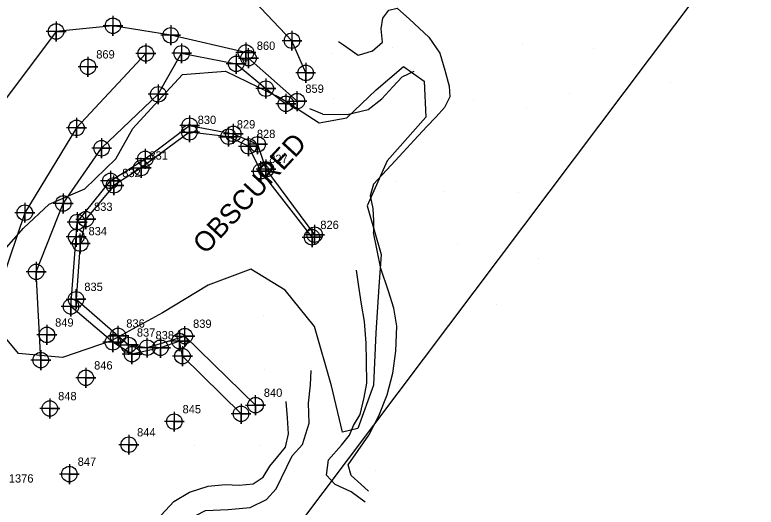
# Model space of a CAD drawing. Extents: x 1497074 to 1501343, y 481943 to 486114.
# Drawn here: x 1498929.9 to 1499153.8, y 484967.5 to 485116.2 of the extents above; entities that cross this region are included whole.
import ezdxf

# ---------------------------------------------------------------- set-up
doc = ezdxf.new("R2010")
doc.units = 0
for name, color, linetype in [('Exist DTM Breakline', 7, 'Continuous'), ('Exist DTM Breakline Cogo Point CELL', 7, 'Continuous'), ('Exist DTM Regular Point CELL', 7, 'Continuous'), ('Exist DTM Regular Point Cogo Number', 7, 'Continuous'), ('Exist Hydro Stream or Body of Water', 7, 'Continuous'), ('Exist Hydro Stream or Body of Water Cogo Number', 7, 'Continuous'), ('Exist Hydro Stream or Body of Water Cogo Point CELL', 7, 'Continuous'), ('PH Exist DTM Boundary', 7, 'Continuous'), ('PH Exist DTM Breakline', 7, 'Continuous'), ('PH Exist DTM Obscure Area', 7, 'Continuous'), ('PH Exist DTM Obscure Area Text', 7, 'Continuous'), ('PH Exist DTM Point', 7, 'Continuous')]:
    doc.layers.add(name, color=color, linetype=linetype)

msp = doc.modelspace()

# ---------------------------------------------------------------- linework, layer by layer
at = {"layer": 'Exist DTM Breakline'}
for points in [[(1499017.74, 485098.64), (1499013.59, 485108.36), (1499002.23, 485120.24), (1498990.16, 485123.16), (1498988.61, 485135.66), (1498984.96, 485153.78)], [(1498999.68, 485104.8), (1498976.97, 485110), (1498959.54, 485112.86), (1498942.37, 485111.16), (1498921.51, 485083.5), (1498907.1, 485054.38), (1498898.24, 485021.36), (1498896.28, 484993.61), (1498898.08, 484985.39)], [(1498969.44, 485104.51), (1498948.52, 485082.03), (1498932.91, 485056.44), (1498921.14, 485021.92), (1498922.42, 484992.91)], [(1498937.73, 485011.92), (1498936.35, 485038.58), (1498944.53, 485059.22), (1498956.11, 485075.89), (1498973.21, 485092.17), (1498980.28, 485104.56), (1498996.74, 485101.37), (1499005.7, 485093.9), (1499011.75, 485089.32)], [(1498979.63, 485017.67), (1498973.87, 485015.66), (1498965.28, 485013.72), (1498959.5, 485017.32), (1498946.85, 485028.12), (1498948.44, 485049.1), (1498948.75, 485053.61), (1498958.76, 485066.03), (1498969.3, 485072.7), (1498982.69, 485082.73), (1498995.88, 485080.22), (1499003.22, 485077.09), (1499005.74, 485069.54), (1499020.42, 485049.78)], [(1498998.21, 484995.71), (1498980.52, 485013.12), (1498979.63, 485017.67)]]:
    msp.add_lwpolyline(points, dxfattribs=at)
at = {"layer": 'Exist DTM Breakline Cogo Point CELL'}
for points in [[(1498959.54, 485115.86), (1498959.54, 485109.86), (1498959.54, 485112.86), (1498962.54, 485112.86), (1498956.54, 485112.86)], [(1498942.37, 485114.16), (1498942.37, 485108.16), (1498942.37, 485111.16), (1498945.37, 485111.16), (1498939.37, 485111.16)], [(1498976.97, 485113), (1498976.97, 485107), (1498976.97, 485110), (1498979.97, 485110), (1498973.97, 485110)], [(1499013.59, 485111.36), (1499013.59, 485105.36), (1499013.59, 485108.36), (1499016.59, 485108.36), (1499010.59, 485108.36)], [(1498969.44, 485107.51), (1498969.44, 485101.51), (1498969.44, 485104.51), (1498972.44, 485104.51), (1498966.44, 485104.51)], [(1498980.28, 485107.56), (1498980.28, 485101.56), (1498980.28, 485104.56), (1498983.28, 485104.56), (1498977.28, 485104.56)], [(1498999.68, 485107.8), (1498999.68, 485101.8), (1498999.68, 485104.8), (1499002.68, 485104.8), (1498996.68, 485104.8)], [(1498996.74, 485104.37), (1498996.74, 485098.37), (1498996.74, 485101.37), (1498999.74, 485101.37), (1498993.74, 485101.37)], [(1499017.74, 485101.64), (1499017.74, 485095.64), (1499017.74, 485098.64), (1499020.74, 485098.64), (1499014.74, 485098.64)], [(1498973.21, 485095.17), (1498973.21, 485089.17), (1498973.21, 485092.17), (1498976.21, 485092.17), (1498970.21, 485092.17)], [(1499005.7, 485096.9), (1499005.7, 485090.9), (1499005.7, 485093.9), (1499008.7, 485093.9), (1499002.7, 485093.9)], [(1499011.75, 485092.32), (1499011.75, 485086.32), (1499011.75, 485089.32), (1499014.75, 485089.32), (1499008.75, 485089.32)], [(1498948.52, 485085.03), (1498948.52, 485079.03), (1498948.52, 485082.03), (1498951.52, 485082.03), (1498945.52, 485082.03)], [(1498982.69, 485085.73), (1498982.69, 485079.73), (1498982.69, 485082.73), (1498985.69, 485082.73), (1498979.69, 485082.73)], [(1498995.88, 485083.22), (1498995.88, 485077.22), (1498995.88, 485080.22), (1498998.88, 485080.22), (1498992.88, 485080.22)], [(1499003.22, 485080.09), (1499003.22, 485074.09), (1499003.22, 485077.09), (1499006.22, 485077.09), (1499000.22, 485077.09)], [(1498956.11, 485078.89), (1498956.11, 485072.89), (1498956.11, 485075.89), (1498959.11, 485075.89), (1498953.11, 485075.89)], [(1498969.3, 485075.7), (1498969.3, 485069.7), (1498969.3, 485072.7), (1498972.3, 485072.7), (1498966.3, 485072.7)], [(1499005.74, 485072.54), (1499005.74, 485066.54), (1499005.74, 485069.54), (1499008.74, 485069.54), (1499002.74, 485069.54)], [(1498958.76, 485069.03), (1498958.76, 485063.03), (1498958.76, 485066.03), (1498961.76, 485066.03), (1498955.76, 485066.03)], [(1498944.53, 485062.22), (1498944.53, 485056.22), (1498944.53, 485059.22), (1498947.53, 485059.22), (1498941.53, 485059.22)], [(1498932.91, 485059.44), (1498932.91, 485053.44), (1498932.91, 485056.44), (1498935.91, 485056.44), (1498929.91, 485056.44)], [(1498948.75, 485056.61), (1498948.75, 485050.61), (1498948.75, 485053.61), (1498951.75, 485053.61), (1498945.75, 485053.61)], [(1499020.42, 485052.78), (1499020.42, 485046.78), (1499020.42, 485049.78), (1499023.42, 485049.78), (1499017.42, 485049.78)], [(1498948.44, 485052.1), (1498948.44, 485046.1), (1498948.44, 485049.1), (1498951.44, 485049.1), (1498945.44, 485049.1)], [(1498936.35, 485041.58), (1498936.35, 485035.58), (1498936.35, 485038.58), (1498939.35, 485038.58), (1498933.35, 485038.58)], [(1498946.85, 485031.12), (1498946.85, 485025.12), (1498946.85, 485028.12), (1498949.85, 485028.12), (1498943.85, 485028.12)], [(1498959.5, 485020.32), (1498959.5, 485014.32), (1498959.5, 485017.32), (1498962.5, 485017.32), (1498956.5, 485017.32)], [(1498979.63, 485020.67), (1498979.63, 485014.67), (1498979.63, 485017.67), (1498982.63, 485017.67), (1498976.63, 485017.67)], [(1498965.28, 485016.72), (1498965.28, 485010.72), (1498965.28, 485013.72), (1498968.28, 485013.72), (1498962.28, 485013.72)], [(1498973.87, 485018.66), (1498973.87, 485012.66), (1498973.87, 485015.66), (1498976.87, 485015.66), (1498970.87, 485015.66)], [(1498937.73, 485014.92), (1498937.73, 485008.92), (1498937.73, 485011.92), (1498940.73, 485011.92), (1498934.73, 485011.92)], [(1498980.52, 485016.12), (1498980.52, 485010.12), (1498980.52, 485013.12), (1498983.52, 485013.12), (1498977.52, 485013.12)], [(1498998.21, 484998.71), (1498998.21, 484992.71), (1498998.21, 484995.71), (1499001.21, 484995.71), (1498995.21, 484995.71)]]:
    msp.add_lwpolyline(points, dxfattribs=at)
for centre in [(1498959.54, 485112.86), (1498942.37, 485111.16), (1498976.97, 485110), (1499013.59, 485108.36), (1498969.44, 485104.51), (1498980.28, 485104.56), (1498999.68, 485104.8), (1498996.74, 485101.37), (1499017.74, 485098.64), (1499005.7, 485093.9), (1498973.21, 485092.17), (1499011.75, 485089.32), (1498948.52, 485082.03), (1498982.69, 485082.73), (1498995.88, 485080.22), (1499003.22, 485077.09), (1498956.11, 485075.89), (1498969.3, 485072.7), (1499005.74, 485069.54), (1498958.76, 485066.03), (1498944.53, 485059.22), (1498932.91, 485056.44), (1498948.75, 485053.61), (1498948.44, 485049.1), (1499020.42, 485049.78), (1498936.35, 485038.58), (1498946.85, 485028.12), (1498959.5, 485017.32), (1498979.63, 485017.67), (1498973.87, 485015.66), (1498965.28, 485013.72), (1498980.52, 485013.12), (1498937.73, 485011.92), (1498998.21, 484995.71)]:
    msp.add_circle(centre, 2.34, dxfattribs=at)
at = {"layer": 'Exist DTM Regular Point CELL'}
for points in [[(1498951.99, 485103.49), (1498951.99, 485097.49), (1498951.99, 485100.49), (1498954.99, 485100.49), (1498948.99, 485100.49)], [(1498939.58, 485022.54), (1498939.58, 485016.54), (1498939.58, 485019.54), (1498942.58, 485019.54), (1498936.58, 485019.54)], [(1498951.35, 485009.59), (1498951.35, 485003.59), (1498951.35, 485006.59), (1498954.35, 485006.59), (1498948.35, 485006.59)], [(1498940.48, 485000.32), (1498940.48, 484994.32), (1498940.48, 484997.32), (1498943.48, 484997.32), (1498937.48, 484997.32)], [(1498978.05, 484996.36), (1498978.05, 484990.36), (1498978.05, 484993.36), (1498981.05, 484993.36), (1498975.05, 484993.36)], [(1498964.32, 484989.39), (1498964.32, 484983.39), (1498964.32, 484986.39), (1498967.32, 484986.39), (1498961.32, 484986.39)], [(1498946.38, 484980.51), (1498946.38, 484974.51), (1498946.38, 484977.51), (1498949.38, 484977.51), (1498943.38, 484977.51)]]:
    msp.add_lwpolyline(points, dxfattribs=at)
for centre in [(1498951.99, 485100.49), (1498939.58, 485019.54), (1498951.35, 485006.59), (1498940.48, 484997.32), (1498978.05, 484993.36), (1498964.32, 484986.39), (1498946.38, 484977.51)]:
    msp.add_circle(centre, 2.34, dxfattribs=at)
at = {"layer": 'Exist Hydro Stream or Body of Water'}
msp.add_line((1499015.12, 485090.12), (1499000.46, 485103.1), dxfattribs=at)
msp.add_lwpolyline([(1499019.65, 485049.02), (1499004.22, 485068.96), (1499000.49, 485076.47), (1498994.43, 485079.37), (1498982.62, 485080.71), (1498968.05, 485069.95), (1498959.84, 485064.68), (1498951.33, 485054.48), (1498949.66, 485047.11), (1498948.39, 485030.3), (1498961.06, 485019.25), (1498964.25, 485016.51), (1498969.89, 485015.7), (1498981.23, 485019.17), (1499002.59, 484998.34)], dxfattribs=at)
at = {"layer": 'Exist Hydro Stream or Body of Water Cogo Point CELL'}
for points in [[(1498997.46, 485103.1), (1499003.46, 485103.1), (1499000.46, 485103.1), (1499000.46, 485100.1), (1499000.46, 485106.1)], [(1499012.12, 485090.12), (1499018.12, 485090.12), (1499015.12, 485090.12), (1499015.12, 485087.12), (1499015.12, 485093.12)], [(1498979.62, 485080.71), (1498985.62, 485080.71), (1498982.62, 485080.71), (1498982.62, 485077.71), (1498982.62, 485083.71)], [(1498991.43, 485079.37), (1498997.43, 485079.37), (1498994.43, 485079.37), (1498994.43, 485076.37), (1498994.43, 485082.37)], [(1498997.49, 485076.47), (1499003.49, 485076.47), (1499000.49, 485076.47), (1499000.49, 485073.47), (1499000.49, 485079.47)], [(1498965.05, 485069.95), (1498971.05, 485069.95), (1498968.05, 485069.95), (1498968.05, 485066.95), (1498968.05, 485072.95)], [(1499001.22, 485068.96), (1499007.22, 485068.96), (1499004.22, 485068.96), (1499004.22, 485065.96), (1499004.22, 485071.96)], [(1498956.84, 485064.68), (1498962.84, 485064.68), (1498959.84, 485064.68), (1498959.84, 485061.68), (1498959.84, 485067.68)], [(1498948.33, 485054.48), (1498954.33, 485054.48), (1498951.33, 485054.48), (1498951.33, 485051.48), (1498951.33, 485057.48)], [(1499016.65, 485049.02), (1499022.65, 485049.02), (1499019.65, 485049.02), (1499019.65, 485046.02), (1499019.65, 485052.02)], [(1498946.66, 485047.11), (1498952.66, 485047.11), (1498949.66, 485047.11), (1498949.66, 485044.11), (1498949.66, 485050.11)], [(1498945.39, 485030.3), (1498951.39, 485030.3), (1498948.39, 485030.3), (1498948.39, 485027.3), (1498948.39, 485033.3)], [(1498958.06, 485019.25), (1498964.06, 485019.25), (1498961.06, 485019.25), (1498961.06, 485016.25), (1498961.06, 485022.25)], [(1498978.23, 485019.17), (1498984.23, 485019.17), (1498981.23, 485019.17), (1498981.23, 485016.17), (1498981.23, 485022.17)], [(1498961.25, 485016.51), (1498967.25, 485016.51), (1498964.25, 485016.51), (1498964.25, 485013.51), (1498964.25, 485019.51)], [(1498966.89, 485015.7), (1498972.89, 485015.7), (1498969.89, 485015.7), (1498969.89, 485012.7), (1498969.89, 485018.7)], [(1498999.59, 484998.34), (1499005.59, 484998.34), (1499002.59, 484998.34), (1499002.59, 484995.34), (1499002.59, 485001.34)]]:
    msp.add_lwpolyline(points, dxfattribs=at)
for centre in [(1499000.46, 485103.1), (1499015.12, 485090.12), (1498982.62, 485080.71), (1498994.43, 485079.37), (1499000.49, 485076.47), (1498968.05, 485069.95), (1499004.22, 485068.96), (1498959.84, 485064.68), (1498951.33, 485054.48), (1499019.65, 485049.02), (1498949.66, 485047.11), (1498948.39, 485030.3), (1498961.06, 485019.25), (1498981.23, 485019.17), (1498964.25, 485016.51), (1498969.89, 485015.7), (1499002.59, 484998.34)]:
    msp.add_circle(centre, 2.34, dxfattribs=at)
at = {"layer": 'PH Exist DTM Boundary'}
msp.add_lwpolyline([(1498924.23, 484841.06), (1498545.19, 485168.9), (1498846.5, 485569.16), (1499227.59, 485244.03)], close=True, dxfattribs=at)
at = {"layer": 'PH Exist DTM Breakline'}
for points in [[(1499037.83, 485105.16), (1499040.94, 485107.91), (1499040.55, 485111.94), (1499041, 485115.16), (1499042.88, 485117.61), (1499045.35, 485118.18), (1499049.03, 485114.84), (1499054.89, 485109.41), (1499058.26, 485104.57), (1499059.74, 485099.51), (1499061.08, 485094.59), (1499061.3, 485091.46), (1499059.68, 485088.23), (1499057.08, 485085.42), (1499054.3, 485082.41), (1499050.52, 485078.33), (1499047.14, 485074.67), (1499043.55, 485070.79), (1499040.79, 485067.83), (1499038.24, 485065.07), (1499037.17, 485061.55), (1499037.99, 485057.71), (1499038.23, 485054.01), (1499038.16, 485050.44)], [(1499037.83, 485105.16), (1499033.53, 485103.91), (1499029.17, 485106.99), (1499027.68, 485108.04)], [(1499022.93, 485086.21), (1499030.28, 485086.1), (1499036.57, 485087.63), (1499040.68, 485090.76), (1499044.05, 485094.4), (1499046.86, 485097.41), (1499050.49, 485099.15)], [(1499022.93, 485086.21), (1499018.99, 485087.82)], [(1499036.7, 484972.33), (1499034.41, 484974.44), (1499031.49, 484977.14), (1499030.58, 484980.35), (1499033.56, 484984.66), (1499036.79, 484989.29), (1499039.83, 484995.06), (1499042.36, 485001.42), (1499044.03, 485008), (1499044.97, 485014.64), (1499045.25, 485022.13), (1499044.32, 485027.62), (1499042.74, 485032.78), (1499040.37, 485039.56), (1499038.16, 485050.44)], [(1499035.67, 484969.09), (1499031.49, 484972.13), (1499026.68, 484974.39), (1499023.97, 484977.18), (1499024.59, 484981.87), (1499028.5, 484986.22), (1499030.91, 484989.29), (1499032.13, 484992.14), (1499034.14, 484995.51), (1499035.36, 485000.64), (1499036.16, 485004.98), (1499036.13, 485011.58), (1499035.98, 485017.02), (1499035.53, 485023.56), (1499034.6, 485028.8), (1499033.78, 485034.16), (1499033.09, 485039.12)], [(1499016.74, 484986.43), (1499018.8, 484992.93), (1499018.54, 484998.93), (1499019.14, 485004.44), (1499019.36, 485008.83), (1499019.36, 485008.84)], [(1498974.06, 484965.14), (1498977.96, 484969.26), (1498982.62, 484972.11), (1498988.26, 484973.87), (1498993.44, 484974.33), (1498997.63, 484974.2), (1499001.88, 484974.58), (1499004.89, 484976.62), (1499006.88, 484979.87), (1499009.3, 484982.82), (1499011.64, 484985.66), (1499012.51, 484989.7), (1499012.28, 484994.5), (1499011.88, 484999.41)], [(1498975.52, 484941.38), (1498971.09, 484939.93), (1498969.09, 484941.66), (1498967.3, 484944.43), (1498968.72, 484949.11), (1498973.3, 484954.59), (1498977.86, 484959.52), (1498981.82, 484963.59), (1498987.43, 484966.51), (1498994.3, 484966.86), (1499000.98, 484967.44), (1499005.87, 484969.89), (1499008.82, 484973.03), (1499013.6, 484983.04), (1499016.74, 484986.43)]]:
    msp.add_lwpolyline(points, dxfattribs=at)
at = {"layer": 'PH Exist DTM Obscure Area'}
for points in [[(1499010.08, 485091.12), (1499021.77, 485083.57), (1499030.12, 485085.05), (1499039.03, 485093.55), (1499047.25, 485100.57), (1499053.53, 485096.15), (1499054.01, 485085.25), (1499042.34, 485072.07), (1499036.25, 485058.49), (1499040.54, 485043.81), (1499039.84, 485034.16), (1499038.89, 485020.17), (1499038.21, 485004.35), (1499033.45, 484991.25), (1499028.84, 484990.22), (1499025.56, 485004.18), (1499020.38, 485022.12), (1499011.52, 485033.01), (1499001.13, 485039.4), (1498988.3, 485034.57), (1498974.45, 485026.19), (1498958.96, 485017.74), (1498944.26, 485012.67), (1498931, 485013.9), (1498921.16, 485025.74)], [(1498923.66, 485041.76), (1498932.55, 485051.81), (1498940.32, 485058.99), (1498951.06, 485063.6), (1498960.42, 485072.7), (1498965.53, 485081.9), (1498973.14, 485090.21), (1498980.55, 485098.19), (1498993.48, 485099.21), (1499010.08, 485091.12)]]:
    msp.add_lwpolyline(points, dxfattribs=at)
at = {"layer": 'PH Exist DTM Point'}
for p, q in [((1499044.06, 485106.37), (1499044.06, 485106.37)), ((1499083.3, 485107.07), (1499083.3, 485107.07)), ((1499124.1, 485106.34), (1499124.1, 485106.34)), ((1499025.93, 485104.64), (1499025.93, 485104.64)), ((1499104.61, 485106.05), (1499104.61, 485106.05)), ((1499127.78, 485095.83), (1499127.78, 485095.83)), ((1499026.11, 485091.02), (1499026.11, 485091.02)), ((1499068.52, 485090.71), (1499068.52, 485090.71)), ((1499097.44, 485092.49), (1499097.44, 485092.49)), ((1499084.47, 485088.31), (1499084.47, 485088.31)), ((1499044.74, 485065.74), (1499044.74, 485065.74)), ((1499059.58, 485062.91), (1499059.58, 485062.91)), ((1499081.87, 485062.57), (1499081.87, 485062.57)), ((1499063.7, 485046.71), (1499063.7, 485046.71)), ((1499088.11, 485042.59), (1499088.11, 485042.59)), ((1499075.28, 485028.71), (1499075.28, 485028.71)), ((1499064.2, 485026.24), (1499064.2, 485026.24)), ((1499004.97, 485025.53), (1499004.97, 485025.53)), ((1499005.25, 485009.18), (1499005.25, 485009.18)), ((1499046.08, 485004.51), (1499046.08, 485004.51)), ((1498984.16, 484986.28), (1498984.16, 484986.28)), ((1499004.18, 484986.26), (1499004.18, 484986.26)), ((1499038.95, 484978.55), (1499038.95, 484978.55))]:
    msp.add_line(p, q, dxfattribs=at)

# ---------------------------------------------------------------- texts
at = {"layer": 'Exist DTM Regular Point Cogo Number'}
for s, p in [('869', (1498954.49, 485102.99)), ('849', (1498942.08, 485022.04)), ('846', (1498953.85, 485009.09)), ('848', (1498942.98, 484999.82)), ('845', (1498980.55, 484995.86)), ('844', (1498966.82, 484988.89)), ('847', (1498948.88, 484980.01)), ('1376', (1498928.1, 484974.96))]:
    msp.add_text(s, height=2.5, dxfattribs=at).set_placement(p)
at = {"layer": 'Exist Hydro Stream or Body of Water Cogo Number'}
for s, p in [('860', (1499002.96, 485105.6)), ('859', (1499017.62, 485092.62)), ('830', (1498985.12, 485083.21)), ('829', (1498996.93, 485081.87)), ('828', (1499002.99, 485078.97)), ('831', (1498970.55, 485072.45)), ('827', (1499006.72, 485071.46)), ('832', (1498962.34, 485067.18)), ('833', (1498953.83, 485056.98)), ('826', (1499022.15, 485051.52)), ('834', (1498952.16, 485049.61)), ('835', (1498950.89, 485032.8)), ('836', (1498963.56, 485021.75)), ('839', (1498983.73, 485021.67)), ('837', (1498966.75, 485019.02)), ('838', (1498972.39, 485018.2)), ('840', (1499005.09, 485000.84))]:
    msp.add_text(s, height=2.5, dxfattribs=at).set_placement(p)
at = {"layer": 'PH Exist DTM Obscure Area Text'}
msp.add_text('OBSCURED', height=6, rotation=47.2398, dxfattribs=at).set_placement((1498987.49, 485043.62))

doc.saveas('drawing.dxf')
